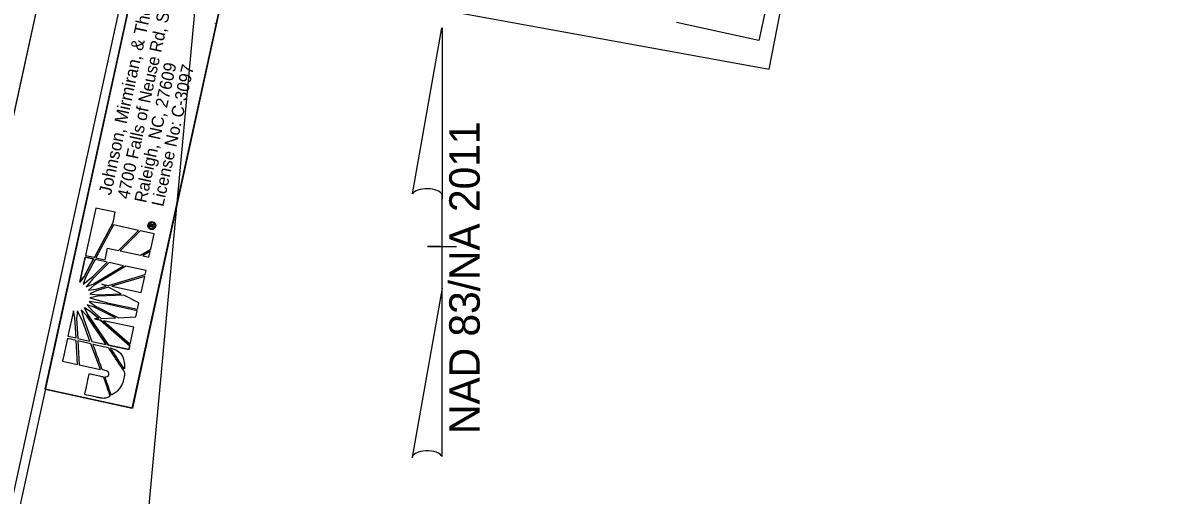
# Model space of a CAD drawing. Extents: x 1615716 to 1617263, y 900664 to 902742.
# Drawn here: x 1616130.6 to 1616450.8, y 902162.6 to 902294.3 of the extents above; entities that cross this region are included whole.
import ezdxf

# ---------------------------------------------------------------- set-up
doc = ezdxf.new("R2010")
doc.units = 0
for name, color, linetype in [('Default', 7, 'Continuous'), ('Exist Structure Minor Pipes RCP 18 Inch', 7, 'Continuous'), ('Prop Drainage Structure Plot Symbol 20 Scale', 7, 'Continuous'), ('Prop Easement Construction', 7, 'Continuous'), ('Prop EOT', 7, 'Continuous'), ('Prop SS Cut Line', 7, 'Continuous'), ('Prop SS Cut Text', 7, 'Continuous'), ('Prop SS Fill Line', 7, 'Continuous'), ('Prop SS Fill Text', 7, 'Continuous')]:
    doc.layers.add(name, color=color, linetype=linetype)

msp = doc.modelspace()

# ---------------------------------------------------------------- linework, layer by layer
at = {"layer": 'Default'}
for p, q in [((1616150.88, 902242.67), (1616148, 902229.45)), ((1616156.29, 902241.49), (1616150.88, 902242.67)), ((1616155.68, 902238.68), (1616156.29, 902241.49)), ((1616150.5, 902228.9), (1616155.68, 902238.68)), ((1616155.78, 902237.96), (1616150.88, 902228.82)), ((1616162.72, 902236.45), (1616155.78, 902237.96)), ((1616165.43, 902238.01), (1616165.63, 902237.97)), ((1616165.63, 902237.97), (1616165.43, 902238.01)), ((1616165.91, 902237.49), (1616166, 902237.89)), ((1616166.88, 902237.28), (1616165.91, 902237.49)), ((1616166, 902237.89), (1616166.01, 902237.95)), ((1616166, 902237.89), (1616166.18, 902237.85)), ((1616166.18, 902237.85), (1616166, 902237.89)), ((1616166.18, 902237.85), (1616166.15, 902237.67)), ((1616166.15, 902237.67), (1616166.37, 902237.62)), ((1616166.19, 902237.87), (1616166.18, 902237.85)), ((1616166.37, 902237.62), (1616166.41, 902237.8)), ((1616166.41, 902237.8), (1616166.41, 902237.81)), ((1616166.41, 902237.8), (1616166.59, 902237.76)), ((1616166.59, 902237.76), (1616166.41, 902237.8)), ((1616166.59, 902237.76), (1616166.55, 902237.58)), ((1616166.55, 902237.58), (1616166.92, 902237.5)), ((1616166.59, 902237.77), (1616166.59, 902237.76)), ((1616166.92, 902237.5), (1616166.88, 902237.28)), ((1616167.34, 902237.6), (1616167.55, 902237.55)), ((1616167.55, 902237.55), (1616167.34, 902237.6)), ((1616167.34, 902237.6), (1616167.34, 902237.6)), ((1616167.55, 902237.56), (1616167.55, 902237.55)), ((1616157.17, 902230.83), (1616162.72, 902236.45)), ((1616163.21, 902236.35), (1616157.69, 902230.72)), ((1616167.11, 902235.5), (1616163.21, 902236.35)), ((1616166.18, 902231.23), (1616167.11, 902235.5)), ((1616153.45, 902228.26), (1616154.15, 902231.49)), ((1616154.15, 902231.49), (1616157.17, 902230.83)), ((1616157.69, 902230.72), (1616163.32, 902229.5)), ((1616163.32, 902229.5), (1616166.18, 902231.23)), ((1616166.05, 902230.61), (1616163.93, 902229.37)), ((1616165.69, 902228.98), (1616166.05, 902230.61)), ((1616147.93, 902228.95), (1616146.38, 902221.99)), ((1616147.59, 902223.57), (1616150.19, 902228.46)), ((1616150.19, 902228.46), (1616147.93, 902228.95)), ((1616148, 902229.45), (1616150.43, 902228.92)), ((1616150.67, 902228.36), (1616148.01, 902223.29)), ((1616154.55, 902227.47), (1616149.94, 902222.81)), ((1616150.07, 902223.57), (1616153.99, 902227.59)), ((1616150.43, 902228.92), (1616150.5, 902228.9)), ((1616153.99, 902227.59), (1616150.67, 902228.36)), ((1616150.88, 902228.82), (1616150.92, 902228.81)), ((1616150.92, 902228.81), (1616153.45, 902228.26)), ((1616158.58, 902226.59), (1616154.55, 902227.47)), ((1616163.93, 902229.37), (1616165.69, 902228.98)), ((1616150.19, 902221.48), (1616158.58, 902226.59)), ((1616159.23, 902226.45), (1616150.44, 902221.14)), ((1616154.43, 902221.07), (1616164.63, 902224.11)), ((1616164.88, 902225.22), (1616159.23, 902226.45)), ((1616164.63, 902224.11), (1616164.88, 902225.22)), ((1616146.38, 902221.99), (1616147.59, 902223.57)), ((1616147.34, 902221.41), (1616150.07, 902223.57)), ((1616148.01, 902223.29), (1616147.34, 902221.41)), ((1616149.94, 902222.81), (1616148.2, 902220.65)), ((1616148.2, 902220.65), (1616150.19, 902221.48)), ((1616150.44, 902221.14), (1616148.79, 902219.74)), ((1616150.97, 902220.07), (1616153.77, 902220.88)), ((1616153.77, 902220.88), (1616152.59, 902221.47)), ((1616152.59, 902221.47), (1616154.43, 902221.07)), ((1616164.49, 902223.6), (1616155.33, 902220.88)), ((1616155.33, 902220.88), (1616163.51, 902219.1)), ((1616163.51, 902219.1), (1616164.49, 902223.6)), ((1616148.79, 902219.74), (1616150.97, 902220.07)), ((1616151.02, 902219.6), (1616149.16, 902218.73)), ((1616149.16, 902218.73), (1616151.22, 902218.5)), ((1616151.42, 902218.05), (1616149.22, 902217.66)), ((1616149.22, 902217.66), (1616154.11, 902216.26)), ((1616154.32, 902220.58), (1616151.02, 902219.6)), ((1616151.22, 902218.5), (1616157.92, 902218.75)), ((1616158.71, 902218.36), (1616151.42, 902218.05)), ((1616157.92, 902218.75), (1616154.32, 902220.58)), ((1616162.88, 902216.18), (1616158.71, 902218.36)), ((1616147.73, 902214.87), (1616148.66, 902212.92)), ((1616149.58, 902213.66), (1616147.73, 902214.87)), ((1616148.49, 902215.65), (1616149.82, 902214.05)), ((1616150.39, 902215.05), (1616148.49, 902215.65)), ((1616154.02, 902215.82), (1616149, 902216.62)), ((1616149, 902216.62), (1616150.82, 902215.33)), ((1616156.32, 902212.05), (1616150.39, 902215.05)), ((1616150.82, 902215.33), (1616157.23, 902212.07)), ((1616162.4, 902213.99), (1616154.02, 902215.82)), ((1616154.11, 902216.26), (1616162.5, 902214.44)), ((1616162.5, 902214.44), (1616162.88, 902216.18)), ((1616144.64, 902213.97), (1616143.1, 902206.9)), ((1616145.04, 902212), (1616144.64, 902213.97)), ((1616145.35, 902206.41), (1616145.04, 902212)), ((1616145.73, 902214), (1616145.53, 902211.89)), ((1616145.53, 902211.89), (1616145.84, 902206.3)), ((1616147.28, 902210.93), (1616145.73, 902214)), ((1616148.26, 902212.72), (1616146.82, 902214.3)), ((1616146.82, 902214.3), (1616147.51, 902211.64)), ((1616147.51, 902211.64), (1616149.79, 902205.44)), ((1616153.72, 902204.59), (1616148.26, 902212.72)), ((1616148.66, 902212.92), (1616154.38, 902204.44)), ((1616151.69, 902211.82), (1616149.58, 902213.66)), ((1616149.82, 902214.05), (1616152.32, 902211.87)), ((1616150.48, 902211.76), (1616151.69, 902211.82)), ((1616152.14, 902211.4), (1616150.48, 902211.76)), ((1616160.31, 902204.24), (1616152.14, 902211.4)), ((1616152.32, 902211.87), (1616156.32, 902212.05)), ((1616157.23, 902212.07), (1616162.03, 902212.27)), ((1616162.03, 902212.27), (1616162.4, 902213.99)), ((1616149.24, 902205.56), (1616147.28, 902210.93)), ((1616161.44, 902209.42), (1616153.05, 902211.2)), ((1616153.05, 902211.2), (1616160.42, 902204.73)), ((1616160.42, 902204.73), (1616161.44, 902209.42)), ((1616142.99, 902206.24), (1616141.62, 902199.95)), ((1616145.42, 902205.71), (1616142.99, 902206.24)), ((1616143.1, 902206.9), (1616145.35, 902206.41)), ((1616145.79, 902199.04), (1616145.42, 902205.71)), ((1616145.84, 902206.3), (1616149.24, 902205.56)), ((1616149.52, 902204.82), (1616145.87, 902205.61)), ((1616145.87, 902205.61), (1616146.27, 902198.94)), ((1616152.13, 902197.66), (1616149.52, 902204.82)), ((1616149.79, 902205.44), (1616153.72, 902204.59)), ((1616154.38, 902204.44), (1616160.09, 902203.2)), ((1616160.09, 902203.2), (1616160.31, 902204.24)), ((1616141.62, 902199.95), (1616145.79, 902199.04)), ((1616146.27, 902198.94), (1616152.13, 902197.66))]:
    msp.add_line(p, q, dxfattribs=at)
for points in [[(1616161.03, 902186.8), (1616190.38, 902321.16), (1616166.14, 902326.45), (1616136.79, 902192.09)], [(1616146.38, 902221.99), (1616147.93, 902228.95), (1616150.19, 902228.46), (1616147.59, 902223.57)], [(1616160.09, 902203.2), (1616154.38, 902204.44), (1616148.66, 902212.92), (1616147.73, 902214.87), (1616149.2, 902213.97), (1616151.69, 902211.82), (1616150.48, 902211.76), (1616152.14, 902211.4), (1616160.31, 902204.24)]]:
    msp.add_lwpolyline(points, close=True, dxfattribs=at)
for points in [[(1616150.88, 902242.67), (1616148, 902229.45), (1616150.43, 902228.92), (1616150.5, 902228.9), (1616155.68, 902238.68), (1616156.29, 902241.49), (1616150.88, 902242.67)], [(1616150.88, 902228.82), (1616150.92, 902228.81), (1616153.45, 902228.26), (1616154.15, 902231.49), (1616157.17, 902230.83), (1616162.72, 902236.45), (1616155.78, 902237.96), (1616150.88, 902228.82)], [(1616166.83, 902238.15), (1616166.88, 902238.13), (1616166.91, 902238.14), (1616166.95, 902238.13), (1616167.06, 902238.13), (1616167.02, 902237.93)], [(1616157.69, 902230.72), (1616163.32, 902229.5), (1616166.18, 902231.23), (1616167.11, 902235.5), (1616163.21, 902236.35), (1616157.69, 902230.72), (1616157.69, 902230.72)], [(1616165.69, 902228.98), (1616165.69, 902228.98), (1616166.05, 902230.61), (1616163.93, 902229.37), (1616165.69, 902228.98)], [(1616147.59, 902223.57), (1616150.19, 902228.46), (1616147.93, 902228.95), (1616146.38, 902221.99), (1616147.59, 902223.57)], [(1616147.34, 902221.41), (1616150.07, 902223.57), (1616153.99, 902227.59), (1616150.67, 902228.36), (1616148.01, 902223.29), (1616147.34, 902221.41)], [(1616148.2, 902220.65), (1616150.19, 902221.48), (1616158.58, 902226.59), (1616154.55, 902227.47), (1616149.94, 902222.81), (1616148.2, 902220.65)], [(1616148.79, 902219.74), (1616150.97, 902220.07), (1616153.77, 902220.88), (1616152.59, 902221.47), (1616154.43, 902221.07), (1616164.63, 902224.11), (1616164.88, 902225.22), (1616159.23, 902226.45), (1616150.44, 902221.14), (1616148.79, 902219.74)], [(1616163.51, 902219.1), (1616164.49, 902223.6), (1616155.33, 902220.88), (1616163.51, 902219.1)], [(1616149.16, 902218.73), (1616151.22, 902218.5), (1616157.92, 902218.75), (1616154.32, 902220.58), (1616151.02, 902219.6), (1616149.16, 902218.73)], [(1616149.22, 902217.66), (1616154.11, 902216.26), (1616162.5, 902214.44), (1616162.88, 902216.18), (1616158.71, 902218.36), (1616151.42, 902218.05), (1616149.22, 902217.66)], [(1616147.73, 902214.87), (1616148.66, 902212.92), (1616154.38, 902204.44), (1616160.09, 902203.2), (1616160.31, 902204.24), (1616152.14, 902211.4), (1616150.48, 902211.76), (1616151.69, 902211.82), (1616149.58, 902213.66), (1616147.73, 902214.87)], [(1616148.49, 902215.65), (1616149.82, 902214.05), (1616152.32, 902211.87), (1616156.32, 902212.05), (1616150.39, 902215.05), (1616148.49, 902215.65)], [(1616150.82, 902215.33), (1616157.23, 902212.07), (1616162.03, 902212.27), (1616162.4, 902213.99), (1616154.02, 902215.82), (1616149, 902216.62), (1616150.82, 902215.33)], [(1616145.04, 902212), (1616144.64, 902213.97), (1616143.1, 902206.9), (1616145.35, 902206.41), (1616145.04, 902212)], [(1616145.84, 902206.3), (1616149.24, 902205.56), (1616147.28, 902210.93), (1616145.73, 902214), (1616145.53, 902211.89), (1616145.84, 902206.3)], [(1616149.79, 902205.44), (1616153.72, 902204.59), (1616148.26, 902212.72), (1616146.82, 902214.3), (1616147.51, 902211.64), (1616149.79, 902205.44)], [(1616160.42, 902204.73), (1616161.44, 902209.42), (1616153.05, 902211.2), (1616160.42, 902204.73)], [(1616145.79, 902199.04), (1616145.42, 902205.71), (1616142.99, 902206.24), (1616141.62, 902199.95), (1616145.79, 902199.04)], [(1616152.13, 902197.66), (1616149.52, 902204.82), (1616145.87, 902205.61), (1616146.27, 902198.94), (1616152.13, 902197.66)]]:
    msp.add_lwpolyline(points, dxfattribs=at)
for points, degree in [([(1616167.55, 902237.55), (1616167.48, 902237.26), (1616167.32, 902237.03), (1616167.07, 902236.87), (1616166.82, 902236.7), (1616166.55, 902236.65), (1616166.25, 902236.72), (1616165.95, 902236.78), (1616165.72, 902236.94), (1616165.57, 902237.19), (1616165.42, 902237.45), (1616165.37, 902237.71), (1616165.43, 902238.01)], 3), ([(1616165.43, 902238.01), (1616165.5, 902238.31), (1616165.66, 902238.54), (1616165.9, 902238.7), (1616166.14, 902238.87), (1616166.42, 902238.92), (1616166.71, 902238.86)], 3), ([(1616165.63, 902237.97), (1616165.58, 902237.73), (1616165.62, 902237.51), (1616165.74, 902237.31), (1616165.87, 902237.11), (1616166.06, 902236.98), (1616166.29, 902236.92), (1616166.53, 902236.87), (1616166.76, 902236.92), (1616166.96, 902237.05), (1616167.16, 902237.18), (1616167.29, 902237.36), (1616167.34, 902237.6)], 3), ([(1616167.34, 902237.6), (1616167.39, 902237.84), (1616167.36, 902238.06), (1616167.23, 902238.26), (1616167.1, 902238.46), (1616166.91, 902238.6), (1616166.67, 902238.65), (1616166.43, 902238.7), (1616166.2, 902238.66), (1616166, 902238.53), (1616165.81, 902238.39), (1616165.69, 902238.21), (1616165.63, 902237.97)], 3), ([(1616166.01, 902237.95), (1616166.07, 902238.19), (1616166.19, 902238.29), (1616166.38, 902238.25), (1616166.47, 902238.23), (1616166.53, 902238.18), (1616166.57, 902238.09)], 3), ([(1616166.41, 902237.81), (1616166.44, 902237.95), (1616166.41, 902238.02), (1616166.34, 902238.04), (1616166.27, 902238.06), (1616166.22, 902238), (1616166.19, 902237.87)], 3), ([(1616166.57, 902238.09), (1616166.62, 902238.15), (1616166.7, 902238.16), (1616166.83, 902238.15)], 2), ([(1616166.66, 902237.93), (1616166.64, 902237.9), (1616166.61, 902237.85), (1616166.59, 902237.77)], 2), ([(1616167.02, 902237.93), (1616166.96, 902237.92), (1616166.9, 902237.91), (1616166.83, 902237.92), (1616166.74, 902237.94), (1616166.69, 902237.95), (1616166.66, 902237.93)], 3), ([(1616166.71, 902238.86), (1616167.01, 902238.79), (1616167.24, 902238.63), (1616167.41, 902238.39), (1616167.56, 902238.13), (1616167.61, 902237.86), (1616167.55, 902237.56)], 3), ([(1616154.48, 902196.21), (1616154.4, 902195.83), (1616154.12, 902195.56), (1616153.4, 902195.57), (1616153.4, 902195.57), (1616155.21, 902190.45), (1616155.21, 902190.45), (1616156.97, 902191.52), (1616158.33, 902193.55), (1616158.74, 902195.43), (1616158.84, 902195.92), (1616158.88, 902196.3), (1616158.89, 902196.84), (1616158.89, 902196.84), (1616154.27, 902203.78), (1616154.27, 902203.78), (1616154.27, 902203.78), (1616150.03, 902204.7), (1616150.03, 902204.7), (1616150.03, 902204.7), (1616152.66, 902197.55), (1616152.66, 902197.55), (1616154.25, 902197.2), (1616154.59, 902196.72), (1616154.48, 902196.21)], 3), ([(1616154.48, 902196.21), (1616154.4, 902195.83), (1616154.12, 902195.56), (1616153.4, 902195.57), (1616153.4, 902195.57), (1616155.21, 902190.45), (1616155.21, 902190.45), (1616156.97, 902191.52), (1616158.33, 902193.55), (1616158.74, 902195.43), (1616158.84, 902195.92), (1616158.88, 902196.3), (1616158.89, 902196.84), (1616158.89, 902196.84), (1616154.27, 902203.78), (1616154.27, 902203.78), (1616154.27, 902203.78), (1616150.03, 902204.7), (1616150.03, 902204.7), (1616150.03, 902204.7), (1616152.66, 902197.55), (1616152.66, 902197.55), (1616154.25, 902197.2), (1616154.59, 902196.72), (1616154.48, 902196.21)], 3), ([(1616154.93, 902203.64), (1616154.93, 902203.64), (1616158.92, 902197.64), (1616158.92, 902197.64), (1616158.85, 902200.17), (1616157.78, 902202.9), (1616154.93, 902203.64)], 3), ([(1616149.04, 902196.44), (1616149.04, 902196.44), (1616147.78, 902190.62), (1616147.78, 902190.62), (1616147.78, 902190.62), (1616151.42, 902189.83), (1616151.42, 902189.83), (1616151.42, 902189.83), (1616151.8, 902189.75), (1616151.8, 902189.75), (1616152.94, 902189.5), (1616153.93, 902189.67), (1616154.83, 902190.17), (1616154.83, 902190.17), (1616152.97, 902195.59), (1616152.89, 902195.61), (1616152.89, 902195.61), (1616149.04, 902196.44), (1616149.04, 902196.44)], 3)]:
    msp.add_open_spline(points, degree=degree, dxfattribs=at)
at = {"layer": 'Exist Structure Minor Pipes RCP 18 Inch'}
msp.add_lwpolyline([(1616136.79, 902192.09), (1616166.12, 902326.45), (1616190.38, 902321.16), (1616161.05, 902186.79)], close=True, dxfattribs=at)
at = {"layer": 'Prop Drainage Structure Plot Symbol 20 Scale'}
msp.add_lwpolyline([(1616850.42, 902379.94), (1617227.49, 902296.2), (1617121.36, 901790.43), (1617088.18, 901641.75), (1617042.44, 901522.26), (1617032.35, 901430.63), (1617021.35, 901334.38), (1616928.77, 900896.77), (1615902.83, 901120.28), (1615974.27, 901386.7), (1616087.67, 901888.92), (1616145.49, 901879.24), (1616184.12, 901827.49), (1616138.37, 901614.97), (1616150.59, 901618.07), (1616181.32, 901620.66), (1616299.19, 901764.2), (1616120.07, 901933.32), (1616161.35, 902112.51), (1616179.69, 902310.42), (1616338.57, 902281.41), (1616353.46, 902358.26)], close=True, dxfattribs=at)
at = {"layer": 'Prop Easement Construction'}
for p, q in [((1616184.13, 902294.2), (1616184.08, 902294.2)), ((1616184.13, 902294.2), (1616184.08, 902294.2)), ((1616239.11, 902246.61), (1616247.31, 902292.96)), ((1616247.36, 902292.96), (1616247.36, 902245.16)), ((1616247.36, 902220.36), (1616247.36, 902246.56)), ((1616247.36, 902245.16), (1616247.36, 902246.51)), ((1616243.36, 902231.96), (1616243.31, 902231.96)), ((1616246.91, 902231.96), (1616243.36, 902231.96)), ((1616243.41, 902231.96), (1616251.41, 902231.96)), ((1616247.36, 902220.36), (1616239.01, 902173.11)), ((1616247.41, 902173.31), (1616247.36, 902220.36))]:
    msp.add_line(p, q, dxfattribs=at)
for centre, start_param, end_param in [((1616243.25, 902246.12), 0.216388, 2.908219), ((1616243.25, 902172.95), 0.201328, 3.141593)]:
    msp.add_ellipse(centre, major_axis=(4.23, -0.03), ratio=0.461098, start_param=start_param, end_param=end_param, dxfattribs=at)
at = {"layer": 'Prop EOT'}
for p, q in [((1616378.34, 902484.88), (1616335.68, 902289.44)), ((1616335.68, 902289.44), (1616312.72, 902294.45))]:
    msp.add_line(p, q, dxfattribs=at)
at = {"layer": 'Prop SS Cut Line'}
msp.add_line((1616187.99, 902543.84), (1615828.85, 900898.58), dxfattribs=at)
at = {"layer": 'Prop SS Cut Text'}
msp.add_lwpolyline([(1616208.96, 902534.66), (1615853.55, 900906.5), (1616884.38, 900681.48), (1617239.79, 902309.64)], close=True, dxfattribs=at)
at = {"layer": 'Prop SS Fill Line'}
msp.add_lwpolyline([(1616208.79, 902521.9), (1615888.89, 901056.41), (1616914.73, 900832.48), (1617234.63, 902297.97)], close=True, dxfattribs=at)
at = {"layer": 'Prop SS Fill Text'}
msp.add_lwpolyline([(1616187.99, 902543.84), (1615828.85, 900898.58), (1616903.54, 900663.99), (1617262.68, 902309.25)], close=True, dxfattribs=at)

# ---------------------------------------------------------------- texts
at = {"layer": 'Default'}
for s, height, p in [('Johnson, Mirmiran, & Thompson Inc.', 3.5139, (1616155.08, 902246.07)), ('4700 Falls of Neuse Rd, Suite 100, ', 3.4135, (1616160.12, 902244.97)), ('Raleigh, NC, 27609', 3.4135, (1616164.89, 902243.93)), ('License No: C-3097', 3.4135, (1616169.65, 902242.89))]:
    msp.add_text(s, height=height, rotation=77.6785, dxfattribs=at).set_placement(p)
at = {"layer": 'Prop Easement Construction'}
msp.add_text('NAD 83/NA 2011', height=8.5, rotation=90, dxfattribs=at).set_placement((1616257.88, 902179.65))

doc.saveas('drawing.dxf')
